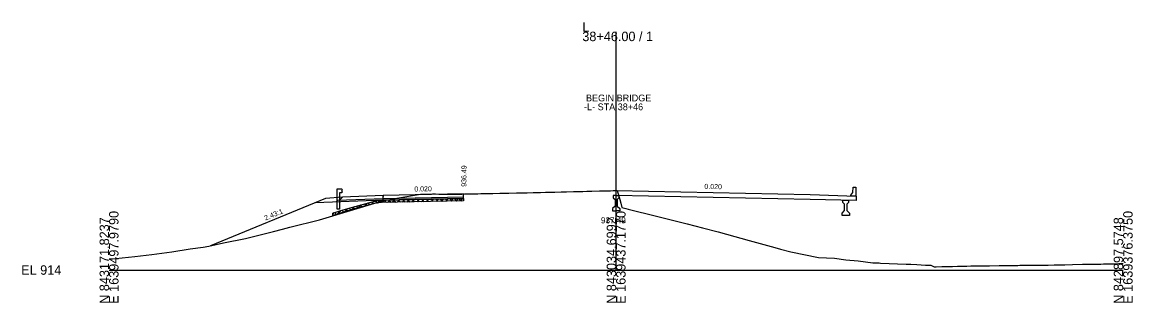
# Model space of a CAD drawing. Extents: x -26 to 1638757, y -10 to 843341.
# Drawn here: x 3624.3 to 3952.8, y -9.7 to 73.3 of the extents above; entities that cross this region are included whole.
import ezdxf

# ---------------------------------------------------------------- set-up
doc = ezdxf.new("R2010")
doc.units = 0
for name, color, linetype in [('Exist Cross Section Cell', 7, 'Continuous'), ('Exist XS Center Line Elevation Label', 7, 'Continuous'), ('Exist XS Ground Line', 7, 'Continuous'), ('Prop CMT Concrete Structures', 7, 'Continuous'), ('Prop CMT Guardrail Widen Shoulder', 7, 'Continuous'), ('Prop CMT Pvmt Course 1', 7, 'Continuous'), ('Prop CMT Pvmt Course 2', 7, 'Continuous'), ('Prop CMT Pvmt Course 3', 7, 'Continuous'), ('Prop CMT Pvmt Surface', 7, 'Continuous'), ('Prop CMT Pvmt Surface Shoulder', 7, 'Continuous'), ('Prop CMT Shld Paved Course 1', 7, 'Continuous'), ('Prop CMT Shld Paved Course 2', 7, 'Continuous'), ('Prop CMT Shld Paved Course 3', 7, 'Continuous'), ('Prop CMT Slope Grass', 7, 'Continuous'), ('Prop CMT Subgrade Earthwork', 7, 'Continuous'), ('Prop XS Label Text', 7, 'Continuous'), ('Prop XS SE Text', 7, 'Continuous'), ('Prop XS Side Slope Text', 7, 'Continuous'), ('Prop XS Undercut Exc Hatch', 7, 'Continuous'), ('Scratch_Level_0', 7, 'Continuous')]:
    doc.layers.add(name, color=color, linetype=linetype)

msp = doc.modelspace()

# ---------------------------------------------------------------- linework, layer by layer
at = {"layer": 'Exist Cross Section Cell'}
for p, q in [((3800, 0), (3800, 70.49)), ((3650, 0), (3800, 0)), ((3800, 0), (3950, 0))]:
    msp.add_line(p, q, dxfattribs=at)
at = {"layer": 'Exist XS Ground Line'}
msp.add_lwpolyline([(3650, 3.21), (3652, 3.4), (3657.59, 4.03), (3662.63, 4.63), (3668.53, 5.42), (3674.01, 6.24), (3677.79, 6.75), (3679.47, 7.02), (3683.81, 7.99), (3690.41, 9.33), (3698.68, 11.41), (3701.35, 12.1), (3703.47, 12.63), (3712.29, 14.89), (3723.35, 18.23), (3730.84, 20.49), (3735.11, 21.25), (3742.15, 22.39), (3742.5, 22.4), (3745.02, 22.48), (3745.7, 22.52), (3746.53, 22.55), (3747.56, 22.48), (3749.08, 22.4), (3750.91, 22.43), (3751.81, 22.44), (3752.49, 22.45), (3752.95, 22.46), (3754.36, 22.48), (3755.15, 22.49), (3755.95, 22.5), (3757.28, 22.53), (3759.11, 22.57), (3760.02, 22.59), (3761.63, 22.62), (3762.75, 22.65), (3763.53, 22.66), (3765.58, 22.7), (3766.98, 22.72), (3767.31, 22.73), (3768.22, 22.73), (3770.56, 22.8), (3770.96, 22.81), (3771.45, 22.82), (3773.69, 22.85), (3775.48, 22.9), (3776.43, 22.92), (3777.62, 22.95), (3779.11, 22.99), (3780.5, 23.02), (3781.9, 23.06), (3783.78, 23.1), (3784.63, 23.12), (3785.3, 23.13), (3787.36, 23.19), (3790.14, 23.25), (3791.32, 23.28), (3791.82, 23.29), (3792.83, 23.32), (3795.13, 23.38), (3796.12, 23.4), (3797.63, 23.43), (3798.3, 23.44), (3799.08, 23.47), (3800, 23.49), (3800.33, 23.5), (3801.06, 20.89), (3801.36, 19.78), (3801.72, 18.47), (3802.87, 18.18), (3803.59, 18), (3811.9, 15.89), (3818.23, 14.32), (3820.97, 13.63), (3825.52, 12.52), (3830.15, 11.27), (3832.64, 10.58), (3839.4, 8.75), (3846.94, 6.66), (3848.64, 6.2), (3851.69, 5.35), (3859.86, 3.66), (3864.63, 3.52), (3868, 3.04), (3871.56, 2.67), (3875.97, 2.14), (3877.77, 2.08), (3878.19, 2.06), (3885.77, 1.76), (3887.15, 1.69), (3888.99, 1.6), (3891.51, 1.47), (3893.11, 1.39), (3894.05, 0.92), (3894.38, 0.93), (3894.7, 0.94), (3896.31, 0.99), (3898.11, 1.03), (3899.49, 1.08), (3900.97, 1.12), (3901.6, 1.12), (3902.22, 1.15), (3903.73, 1.15), (3904.96, 1.19), (3905.63, 1.21), (3907.14, 1.22), (3907.69, 1.23), (3909.42, 1.27), (3910.43, 1.28), (3913.3, 1.32), (3915.9, 1.35), (3917.96, 1.37), (3918.81, 1.38), (3919.47, 1.39), (3921.57, 1.41), (3922.95, 1.43), (3923.46, 1.43), (3924.1, 1.44), (3924.57, 1.45), (3925.64, 1.46), (3926.41, 1.46), (3926.84, 1.47), (3927.79, 1.48), (3929.57, 1.5), (3931.81, 1.56), (3932.31, 1.57), (3932.7, 1.58), (3935.04, 1.62), (3937.97, 1.69), (3940.51, 1.73), (3942.53, 1.76), (3943.39, 1.77), (3944.15, 1.79), (3945.32, 1.82), (3945.85, 1.83), (3946.68, 1.85), (3947.77, 1.87), (3948.71, 1.88), (3950, 1.91)], dxfattribs=at)
at = {"layer": 'Prop CMT Concrete Structures'}
for points in [[(3800, 22.01), (3800, 23.51)], [(3800, 23.51), (3857.41, 22.36), (3871.03, 21.82)], [(3800, 22.01), (3800, 23.51)], [(3869.41, 21.88), (3869.41, 22.13), (3869.99, 22.91), (3870.16, 24.49), (3870.91, 24.49), (3870.91, 21.82)], [(3800, 22.01), (3799.17, 21.99)], [(3799.17, 21.99), (3799.17, 21.34)], [(3799.17, 21.34), (3799.67, 20.84)], [(3799.67, 20.84), (3799.67, 18.93)], [(3800, 22.01), (3800.83, 21.99)], [(3871.03, 20.59), (3857.41, 20.86), (3800, 22.01)], [(3800.83, 21.34), (3800.33, 20.84)], [(3800.33, 20.84), (3800.33, 18.93)], [(3800.83, 21.99), (3800.83, 21.34)], [(3867.07, 20.67), (3867.91, 20.65), (3868.74, 20.64)], [(3867.07, 19.99), (3867.07, 20.67)], [(3867.57, 19.48), (3867.07, 19.99)], [(3868.74, 19.99), (3868.24, 19.48)], [(3868.74, 20.64), (3868.74, 19.99)], [(3870.91, 21.82), (3869.41, 21.88)], [(3871.03, 21.82), (3871.03, 20.59)], [(3799.67, 18.93), (3798.92, 18.18)], [(3798.92, 18.18), (3798.92, 17.51)], [(3798.92, 17.51), (3800, 17.51)], [(3801.08, 17.51), (3800, 17.51)], [(3800.33, 18.93), (3801.08, 18.18)], [(3801.08, 18.18), (3801.08, 17.51)], [(3866.82, 16.82), (3867.57, 17.57)], [(3866.82, 16.15), (3866.82, 16.82)], [(3867.57, 17.57), (3867.57, 19.48)], [(3868.24, 19.48), (3868.24, 17.57)], [(3868.24, 17.57), (3868.99, 16.82)], [(3868.99, 16.82), (3868.99, 16.15)], [(3868.99, 16.15), (3867.91, 16.15), (3866.82, 16.15)]]:
    msp.add_lwpolyline(points, dxfattribs=at)
at = {"layer": 'Prop CMT Guardrail Widen Shoulder'}
for points in [[(3717.45, 18.03), (3717.45, 24.03)], [(3717.45, 24.03), (3718.79, 24.03), (3719.06, 23.74)], [(3719.06, 23.16), (3718.79, 22.87), (3718.12, 22.87)], [(3719.06, 23.74), (3718.79, 23.45)], [(3718.79, 23.45), (3719.06, 23.16)], [(3718.12, 22.87), (3718.12, 18.03)], [(3718.12, 18.03), (3717.45, 18.03)]]:
    msp.add_lwpolyline(points, dxfattribs=at)
at = {"layer": 'Prop CMT Pvmt Course 1'}
for points in [[(3754.86, 22.49), (3731.04, 22.01)], [(3731.04, 22.01), (3731.04, 21.76)], [(3754.86, 22.24), (3754.86, 22.49)]]:
    msp.add_lwpolyline(points, dxfattribs=at)
at = {"layer": 'Prop CMT Pvmt Course 2'}
msp.add_lwpolyline([(3754.86, 21.53), (3754.86, 22.24)], dxfattribs=at)
at = {"layer": 'Prop CMT Pvmt Course 3'}
msp.add_lwpolyline([(3754.86, 21.12), (3754.86, 21.53)], dxfattribs=at)
at = {"layer": 'Prop CMT Pvmt Surface'}
msp.add_lwpolyline([(3754.86, 22.49), (3731.04, 22.01)], dxfattribs=at)
at = {"layer": 'Prop CMT Pvmt Surface Shoulder'}
msp.add_line((3731.04, 22.01), (3719.04, 21.53), dxfattribs=at)
at = {"layer": 'Prop CMT Shld Paved Course 1'}
for p, q in [((3719.04, 21.53), (3718.79, 21.28)), ((3731.04, 22.01), (3719.04, 21.53))]:
    msp.add_line(p, q, dxfattribs=at)
msp.add_lwpolyline([(3731.04, 21.76), (3731.04, 22.01)], dxfattribs=at)
at = {"layer": 'Prop CMT Shld Paved Course 2'}
msp.add_line((3718.79, 21.28), (3718.04, 20.54), dxfattribs=at)
msp.add_lwpolyline([(3731.04, 21.06), (3731.04, 21.76)], dxfattribs=at)
at = {"layer": 'Prop CMT Shld Paved Course 3'}
for p, q in [((3717.53, 20.51), (3717.14, 20.12)), ((3731.04, 21.06), (3717.53, 20.51)), ((3754.86, 21.53), (3731.04, 21.06))]:
    msp.add_line(p, q, dxfattribs=at)
msp.add_lwpolyline([(3731.04, 20.64), (3731.04, 21.06)], dxfattribs=at)
at = {"layer": 'Prop CMT Slope Grass'}
msp.add_lwpolyline([(3719.04, 21.53), (3714.04, 21.13), (3679.99, 7.11)], dxfattribs=at)
at = {"layer": 'Prop CMT Subgrade Earthwork'}
for p, q in [((3731.04, 20.64), (3711.03, 19.89)), ((3754.86, 21.12), (3754.86, 22.43))]:
    msp.add_line(p, q, dxfattribs=at)
msp.add_lwpolyline([(3754.86, 21.12), (3731.04, 20.64)], dxfattribs=at)
at = {"layer": 'Prop XS Undercut Exc Hatch'}
for p, q in [((3721.74, 18.52), (3728.26, 20.3)), ((3725.56, 18.87), (3726.52, 19.82)), ((3726.55, 19.83), (3727.1, 19.29)), ((3727.51, 19.4), (3728.43, 20.32)), ((3727.66, 20.13), (3728.21, 19.59)), ((3728.26, 20.3), (3730.28, 20.61)), ((3728.83, 20.38), (3729.42, 19.79)), ((3729.3, 19.78), (3730.1, 20.58)), ((3730.06, 20.57), (3730.66, 19.96)), ((3730.28, 20.61), (3731.04, 20.64)), ((3754.87, 20.45), (3730.49, 19.96)), ((3730.91, 19.97), (3731.59, 20.65)), ((3731.04, 20.64), (3754.86, 21.12)), ((3731.39, 20.65), (3732.05, 19.99)), ((3732.35, 20), (3733.03, 20.68)), ((3732.78, 20.67), (3733.44, 20.02)), ((3733.79, 20.02), (3734.48, 20.71)), ((3734.17, 20.7), (3734.82, 20.04)), ((3735.23, 20.05), (3735.92, 20.74)), ((3735.55, 20.73), (3736.21, 20.07)), ((3736.68, 20.08), (3737.36, 20.77)), ((3736.94, 20.76), (3737.6, 20.1)), ((3738.12, 20.11), (3738.8, 20.79)), ((3738.33, 20.79), (3738.98, 20.13)), ((3739.56, 20.14), (3740.25, 20.82)), ((3739.71, 20.81), (3740.37, 20.16)), ((3741.01, 20.17), (3741.69, 20.85)), ((3741.1, 20.84), (3741.76, 20.18)), ((3742.45, 20.2), (3743.13, 20.88)), ((3742.49, 20.87), (3743.14, 20.21)), ((3743.87, 20.9), (3744.53, 20.24)), ((3743.89, 20.23), (3744.58, 20.91)), ((3745.26, 20.92), (3745.92, 20.27)), ((3745.34, 20.25), (3746.02, 20.94)), ((3746.65, 20.95), (3747.3, 20.29)), ((3746.78, 20.28), (3747.46, 20.97)), ((3748.03, 20.98), (3748.69, 20.32)), ((3748.22, 20.31), (3748.91, 21)), ((3749.42, 21.01), (3750.08, 20.35)), ((3749.66, 20.34), (3750.35, 21.03)), ((3750.8, 21.03), (3751.46, 20.38)), ((3751.11, 20.37), (3751.79, 21.05)), ((3752.19, 21.06), (3752.85, 20.41)), ((3752.55, 20.4), (3753.23, 21.08)), ((3753.58, 21.09), (3754.23, 20.43)), ((3753.99, 20.43), (3754.68, 21.11)), ((3754.86, 21.12), (3754.87, 20.45)), ((3716.16, 16.84), (3718.3, 17.49)), ((3716.16, 16.54), (3716.59, 16.97)), ((3716.16, 16.14), (3716.16, 16.84)), ((3716.66, 16.99), (3717.2, 16.45)), ((3717.62, 16.58), (3718.64, 17.6)), ((3717.75, 17.32), (3718.28, 16.79)), ((3718.3, 17.49), (3720.68, 18.23)), ((3718.83, 17.66), (3719.36, 17.12)), ((3719.67, 17.21), (3720.68, 18.23)), ((3719.91, 17.99), (3720.44, 17.45)), ((3720.68, 18.23), (3721.74, 18.52)), ((3721, 18.32), (3721.54, 17.77)), ((3721.67, 17.81), (3722.63, 18.76)), ((3722.11, 18.62), (3722.65, 18.07)), ((3723.22, 18.92), (3723.76, 18.38)), ((3723.62, 18.34), (3724.57, 19.29)), ((3724.33, 19.23), (3724.88, 18.68)), ((3725.44, 19.53), (3725.99, 18.98))]:
    msp.add_line(p, q, dxfattribs=at)
msp.add_lwpolyline([(3730.49, 19.96), (3728.4, 19.64), (3721.92, 17.87), (3720.87, 17.59), (3718.5, 16.85), (3716.16, 16.14)], dxfattribs=at)

# ---------------------------------------------------------------- texts
at = {"layer": 'Exist Cross Section Cell'}
for s, p in [('L', (3790, 70.49)), ('38+46.00 / 1', (3790, 67.69)), ('EL 914', (3624, -1.4))]:
    msp.add_text(s, height=2.8, dxfattribs=at).set_placement(p)
for s, p in [('E 1639497.9790', (3652.8, -10)), ('E 1639437.1770', (3802.8, -10)), ('E 1639376.3750', (3952.8, -10)), ('N 843171.8237', (3650, -10)), ('N 843034.6992', (3800, -10)), ('N 842897.5748', (3950, -10))]:
    msp.add_text(s, height=2.8, rotation=90, dxfattribs=at).set_placement(p)
at = {"layer": 'Exist XS Center Line Elevation Label'}
msp.add_text('937.49', height=1.8, dxfattribs=at).set_placement((3795.51, 13.8))
at = {"layer": 'Prop XS Label Text'}
for s, p in [('-L- STA 38+46', (3790.52, 47.26)), ('BEGIN BRIDGE', (3791.09, 49.88))]:
    msp.add_text(s, height=2, dxfattribs=at).set_placement(p)
at = {"layer": 'Prop XS SE Text'}
for s, rotation, p in [('936.49', 89.6864, (3755.71, 24.61)), ('0.020', 1.145, (3740.31, 23.2)), ('0.020', 358.8544, (3826.1, 23.99))]:
    msp.add_text(s, height=1.5, rotation=rotation, dxfattribs=at).set_placement(p)
at = {"layer": 'Prop XS Side Slope Text'}
msp.add_text('2.43:1', height=1.5, rotation=22.3866, dxfattribs=at).set_placement((3696.29, 14.63))
at = {"layer": 'Scratch_Level_0'}
msp.add_text('LT_GS_OS_CTL', height=0.01, dxfattribs=at).set_placement((3718.01, 21.39))

doc.saveas('drawing.dxf')
